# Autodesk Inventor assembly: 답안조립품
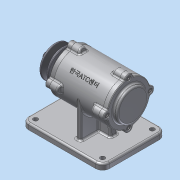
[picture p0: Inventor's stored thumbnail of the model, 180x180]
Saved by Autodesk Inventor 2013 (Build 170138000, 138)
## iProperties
Created: 2015-12
Part Number: 답안조립품
Document SubType Name: Assembly
Designer: Administrator
Author: Administrator
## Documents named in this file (11)
- C:\Users\Administrator\Desktop\451208V1026\답안조립품.iam
- C:\Users\Administrator\Desktop\451208V1026\본체.ipt
- C:\Users\Administrator\Desktop\451208V1026\커버.ipt
- C:\Users\Administrator\Desktop\451208V1026\커버2.ipt
- C:\Users\Administrator\Desktop\451208V1026\볼트 M4 x 12.ipt
- C:\Users\Administrator\Desktop\451208V1026\베어링 6204.ipt
- C:\Users\Administrator\Desktop\451208V1026\오일실.ipt
- C:\Users\Administrator\Desktop\451208V1026\축.ipt
- C:\Users\Administrator\Desktop\451208V1026\키(4 x 4 x 12).ipt
- C:\Users\Administrator\Desktop\451208V1026\V-벨트풀리.ipt
- C:\Users\Administrator\Desktop\451208V1026\너트 M12x1.25.ipt
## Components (6 placed, 5 different names)
1. KS B 2023 6204 - 20 x 47 x 14:1
2. KS B 2023 6204 - 20 x 47 x 14:2
3. KS B 2804 D D - 20 32 8:1
4. KS B 1311 (I) 4 x 4 x 12:1 — 각도:1
5. V-벨트풀리:1 — 각도:1
6. KS B 1012 클래스 1 일반 - 미터 M12x1.25:1
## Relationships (1: Angle 1)
- 각도:1 [Angle]: KS B 1311 (I) 4 x 4 x 12:1 ↔ V-벨트풀리:1
